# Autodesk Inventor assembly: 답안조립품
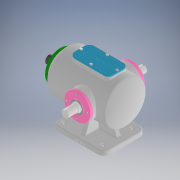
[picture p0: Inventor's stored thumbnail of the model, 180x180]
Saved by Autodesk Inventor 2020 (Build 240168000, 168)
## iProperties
Created: 2021-11
Part Number: 답안조립품
Document SubType Name: Assembly
Designer: Administrator
Author: Administrator
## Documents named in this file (15)
- C:\Users\Administrator\Desktop\711106V1029\답안조립품.iam
- C:\Users\Administrator\Desktop\711106V1029\본체.ipt
- C:\Users\Administrator\Desktop\711106V1029\베어링 6205.ipt
- 베어링 6205.ipt
- C:\Users\Administrator\Desktop\711106V1029\볼트 M4x0.7.ipt
- C:\Users\Administrator\Desktop\711106V1029\부시.ipt
- C:\Users\Administrator\Desktop\711106V1029\상부커버.ipt
- C:\Users\Administrator\Desktop\711106V1029\슬라이드 커버.ipt
- C:\Users\Administrator\Desktop\711106V1029\슬라이드.ipt
- C:\Users\Administrator\Desktop\711106V1029\오일실.ipt
- 오일실.ipt
- C:\Users\Administrator\Desktop\711106V1029\육각머리볼트 M4.ipt
- C:\Users\Administrator\Desktop\711106V1029\축 커버.ipt
- C:\Users\Administrator\Desktop\711106V1029\편심축.ipt
- C:\Users\Administrator\Desktop\711106V1029\축 커버_MIR.ipt
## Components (12 placed, 1 different names)
1. M4x0.7:1
2. M4x0.7:2
3. M4x0.7:3
4. M4x0.7:4
5. M4x0.7:5 — 각도:2
6. M4x0.7:6
7. M4x0.7:7
8. M4x0.7:8
9. M4x0.7:9
10. M4x0.7:10
11. M4x0.7:11
12. M4x0.7:12 — 각도:1
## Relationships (2: Angle 2)
- 각도:1 [Angle]: M4x0.7:12
- 각도:2 [Angle]: M4x0.7:5
